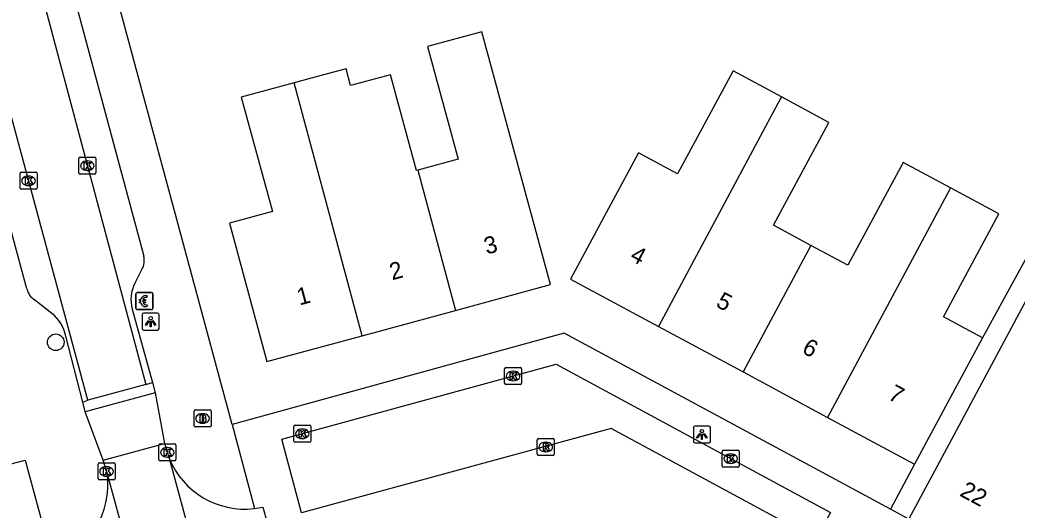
# Model space of a CAD drawing. Extents: x 159265 to 160143, y 383413 to 384319.
# Drawn here: x 159811.3 to 159869.9, y 383863.5 to 383892.3 of the extents above; entities that cross this region are included whole.
import ezdxf

# ---------------------------------------------------------------- set-up
doc = ezdxf.new("R2010")
doc.units = 0
for name, color, linetype in [('IMGEO_Betaalautomaat', 7, 'Continuous'), ('IMGEO_Boom', 7, 'Continuous'), ('IMGEO_Brandkraan', 7, 'Continuous'), ('IMGEO_Kolk', 7, 'Continuous'), ('IMGEO_Lichtpunt', 7, 'Continuous'), ('IMGEO_Pand', 7, 'Continuous'), ('IMGEO_Pand_nummerreeks', 7, 'Continuous'), ('IMGEO_Rijbaan_lokaal_open', 7, 'Continuous'), ('IMGEO_Rioolput', 7, 'Continuous'), ('IMGEO_Voetpad_open', 7, 'Continuous')]:
    doc.layers.add(name, color=color, linetype=linetype)

msp = doc.modelspace()

# ---------------------------------------------------------------- linework, layer by layer
at = {"layer": 'IMGEO_Betaalautomaat'}
for p, q in [((159818.135, 383875.319), (159818.135, 383876.16)), ((159818.135, 383876.16), (159818.135, 383875.319)), ((159818.21, 383876.243), (159819.051, 383876.243)), ((159819.051, 383876.243), (159818.21, 383876.243)), ((159818.418, 383875.707), (159818.418, 383875.775)), ((159818.539, 383875.775), (159818.539, 383875.707)), ((159818.797, 383876.048), (159818.78, 383875.948)), ((159819.134, 383876.169), (159819.134, 383875.328)), ((159819.134, 383875.328), (159819.134, 383876.169)), ((159819.06, 383875.244), (159818.219, 383875.244)), ((159818.219, 383875.244), (159819.06, 383875.244)), ((159818.784, 383875.542), (159818.806, 383875.455))]:
    msp.add_line(p, q, dxfattribs=at)
for points in [[(159818.418, 383875.775), (159818.349, 383875.775), (159818.349, 383875.844), (159818.428, 383875.844)], [(159818.423, 383875.638), (159818.349, 383875.638), (159818.349, 383875.707), (159818.418, 383875.707)], [(159818.55, 383875.844), (159818.697, 383875.844), (159818.697, 383875.775), (159818.539, 383875.775)], [(159818.539, 383875.707), (159818.697, 383875.707), (159818.697, 383875.638), (159818.553, 383875.638)]]:
    msp.add_lwpolyline(points, dxfattribs=at)
for centre, radius, start, end in [((159818.213, 383876.166), 0.0779, 92.4484, 184.28452), ((159818.213, 383876.166), 0.0779, 92.4484, 184.28452), ((159818.711, 383875.768), 0.293, 73.01398, 165.01395), ((159818.717, 383875.781), 0.179, 69.32359, 159.56827), ((159819.057, 383876.166), 0.0779, 2.4484, 94.28452), ((159819.057, 383876.166), 0.0779, 2.4484, 94.28452), ((159818.213, 383875.322), 0.0779, 182.4484, 274.28452), ((159818.213, 383875.322), 0.0779, 182.4484, 274.28452), ((159818.684, 383875.693), 0.267, 191.80956, 297.03891), ((159818.717, 383875.708), 0.179, 202.76249, 291.86925), ((159819.057, 383875.322), 0.0779, 272.4484, 4.28452), ((159819.057, 383875.322), 0.0779, 272.4484, 4.28452)]:
    msp.add_arc(centre, radius, start, end, dxfattribs=at)
at = {"layer": 'IMGEO_Boom'}
msp.add_circle((159813.417, 383873.324), 0.489, dxfattribs=at)
at = {"layer": 'IMGEO_Brandkraan'}
for p, q in [((159821.552, 383868.422), (159821.552, 383869.274)), ((159821.627, 383869.348), (159822.479, 383869.348)), ((159822.553, 383869.274), (159822.553, 383868.422)), ((159822.04, 383869.128), (159822.065, 383869.128)), ((159822.479, 383868.348), (159821.627, 383868.348)), ((159822.063, 383868.568), (159822.038, 383868.568))]:
    msp.add_line(p, q, dxfattribs=at)
for points in [[(159821.552, 383868.422), (159821.552, 383869.274)], [(159821.627, 383869.348), (159822.479, 383869.348)], [(159822.553, 383869.274), (159822.553, 383868.422)], [(159821.9, 383869.048), (159821.9, 383868.648), (159822.113, 383868.648)], [(159822.131, 383869.048), (159821.9, 383869.048)], [(159822.079, 383868.967), (159822.025, 383868.967), (159822.025, 383868.891)], [(159822.025, 383868.891), (159822.078, 383868.891)], [(159822.087, 383868.815), (159822.025, 383868.815), (159822.025, 383868.734)], [(159822.025, 383868.734), (159822.087, 383868.734)], [(159822.479, 383868.348), (159821.627, 383868.348)]]:
    msp.add_lwpolyline(points, dxfattribs=at)
for centre, radius, start, end in [((159821.629, 383869.272), 0.0765, 91.55205, 178.44795), ((159821.629, 383869.272), 0.0765, 91.55205, 178.44795), ((159822.477, 383869.272), 0.0765, 1.55205, 88.44795), ((159822.477, 383869.272), 0.0765, 1.55205, 88.44795), ((159822.08, 383868.929), 0.0379, 267.82845, 90.93552), ((159822.088, 383868.774), 0.0404, 269.87594, 90.50774), ((159822.119, 383868.899), 0.251, 268.66757, 293.53466), ((159822.135, 383868.903), 0.145, 59.4692, 91.53667), ((159822.16, 383868.95), 0.0922, 285.51372, 58.15012), ((159822.165, 383868.758), 0.105, 301.31148, 78.98903), ((159821.629, 383868.424), 0.0765, 181.55205, 268.44795), ((159821.629, 383868.424), 0.0765, 181.55205, 268.44795), ((159822.477, 383868.424), 0.0765, 271.55205, 358.44795), ((159822.477, 383868.424), 0.0765, 271.55205, 358.44795)]:
    msp.add_arc(centre, radius, start, end, dxfattribs=at)
for centre, major_axis, ratio, start_param, end_param in [((159822.039, 383868.848), (-0.387, 0.002), 0.722429, 4.712389, 7.853982), ((159822.064, 383868.848), (-0.39, 0.002), 0.717154, 1.570796, 4.712389)]:
    msp.add_ellipse(centre, major_axis=major_axis, ratio=ratio, start_param=start_param, end_param=end_param, dxfattribs=at)
at = {"layer": 'IMGEO_Kolk'}
for p, q in [((159814.779, 383883.275), (159814.779, 383884.127)), ((159814.854, 383884.201), (159815.706, 383884.201)), ((159815.267, 383883.981), (159815.292, 383883.981)), ((159815.78, 383884.127), (159815.78, 383883.275)), ((159811.395, 383883.316), (159812.247, 383883.316)), ((159815.29, 383883.421), (159815.265, 383883.421)), ((159811.32, 383882.39), (159811.32, 383883.242)), ((159811.808, 383883.096), (159811.833, 383883.096)), ((159812.321, 383883.242), (159812.321, 383882.39)), ((159815.706, 383883.201), (159814.854, 383883.201)), ((159812.247, 383882.316), (159811.395, 383882.316)), ((159811.831, 383882.536), (159811.806, 383882.536)), ((159839.813, 383870.913), (159839.813, 383871.765)), ((159839.888, 383871.839), (159840.74, 383871.839)), ((159840.301, 383871.619), (159840.326, 383871.619)), ((159840.814, 383871.765), (159840.814, 383870.913)), ((159840.324, 383871.059), (159840.299, 383871.059)), ((159840.74, 383870.839), (159839.888, 383870.839)), ((159827.415, 383867.521), (159827.415, 383868.373)), ((159827.49, 383868.447), (159828.342, 383868.447)), ((159827.903, 383868.227), (159827.928, 383868.227)), ((159828.416, 383868.373), (159828.416, 383867.521)), ((159827.926, 383867.667), (159827.901, 383867.667)), ((159819.478, 383866.425), (159819.478, 383867.277)), ((159819.553, 383867.351), (159820.405, 383867.351)), ((159819.966, 383867.131), (159819.991, 383867.131)), ((159820.479, 383867.277), (159820.479, 383866.425)), ((159828.342, 383867.447), (159827.49, 383867.447)), ((159852.604, 383866.06), (159852.604, 383866.912)), ((159852.679, 383866.986), (159853.531, 383866.986)), ((159853.605, 383866.912), (159853.605, 383866.06)), ((159820.405, 383866.351), (159819.553, 383866.351)), ((159819.989, 383866.571), (159819.964, 383866.571)), ((159853.092, 383866.766), (159853.117, 383866.766)), ((159815.908, 383865.306), (159815.908, 383866.158)), ((159815.983, 383866.232), (159816.835, 383866.232)), ((159816.396, 383866.012), (159816.421, 383866.012)), ((159816.909, 383866.158), (159816.909, 383865.306)), ((159853.531, 383865.986), (159852.679, 383865.986)), ((159853.115, 383866.206), (159853.09, 383866.206)), ((159816.835, 383865.232), (159815.983, 383865.232)), ((159816.419, 383865.452), (159816.394, 383865.452))]:
    msp.add_line(p, q, dxfattribs=at)
for points in [[(159814.779, 383883.275), (159814.779, 383884.127)], [(159814.854, 383884.201), (159815.706, 383884.201)], [(159815.1, 383883.901), (159815.223, 383883.901), (159815.223, 383883.75), (159815.353, 383883.901), (159815.517, 383883.901), (159815.371, 383883.75), (159815.524, 383883.501), (159815.372, 383883.501), (159815.287, 383883.665), (159815.223, 383883.598), (159815.223, 383883.501), (159815.1, 383883.501), (159815.1, 383883.901)], [(159815.78, 383884.127), (159815.78, 383883.275)], [(159811.395, 383883.316), (159812.247, 383883.316)], [(159811.32, 383882.39), (159811.32, 383883.242)], [(159811.641, 383883.016), (159811.764, 383883.016), (159811.764, 383882.865), (159811.894, 383883.016), (159812.058, 383883.016), (159811.912, 383882.865), (159812.065, 383882.616), (159811.913, 383882.616), (159811.828, 383882.78), (159811.764, 383882.713), (159811.764, 383882.616), (159811.641, 383882.616), (159811.641, 383883.016)], [(159812.321, 383883.242), (159812.321, 383882.39)], [(159815.706, 383883.201), (159814.854, 383883.201)], [(159812.247, 383882.316), (159811.395, 383882.316)], [(159839.813, 383870.913), (159839.813, 383871.765)], [(159839.888, 383871.839), (159840.74, 383871.839)], [(159840.814, 383871.765), (159840.814, 383870.913)], [(159840.134, 383871.539), (159840.257, 383871.539), (159840.257, 383871.388), (159840.387, 383871.539), (159840.551, 383871.539), (159840.405, 383871.388), (159840.558, 383871.139), (159840.406, 383871.139), (159840.321, 383871.303), (159840.257, 383871.236), (159840.257, 383871.139), (159840.134, 383871.139), (159840.134, 383871.539)], [(159840.74, 383870.839), (159839.888, 383870.839)], [(159827.415, 383867.521), (159827.415, 383868.373)], [(159827.49, 383868.447), (159828.342, 383868.447)], [(159827.736, 383868.147), (159827.859, 383868.147), (159827.859, 383867.996), (159827.989, 383868.147), (159828.153, 383868.147), (159828.007, 383867.996), (159828.16, 383867.747), (159828.008, 383867.747), (159827.923, 383867.911), (159827.859, 383867.844), (159827.859, 383867.747), (159827.736, 383867.747), (159827.736, 383868.147)], [(159828.416, 383868.373), (159828.416, 383867.521)], [(159819.478, 383866.425), (159819.478, 383867.277)], [(159819.553, 383867.351), (159820.405, 383867.351)], [(159819.799, 383867.051), (159819.922, 383867.051), (159819.922, 383866.9), (159820.052, 383867.051), (159820.216, 383867.051), (159820.07, 383866.9), (159820.223, 383866.651), (159820.071, 383866.651), (159819.986, 383866.815), (159819.922, 383866.748), (159819.922, 383866.651), (159819.799, 383866.651), (159819.799, 383867.051)], [(159820.479, 383867.277), (159820.479, 383866.425)], [(159828.342, 383867.447), (159827.49, 383867.447)], [(159852.604, 383866.06), (159852.604, 383866.912)], [(159852.679, 383866.986), (159853.531, 383866.986)], [(159853.605, 383866.912), (159853.605, 383866.06)], [(159820.405, 383866.351), (159819.553, 383866.351)], [(159852.925, 383866.686), (159853.048, 383866.686), (159853.048, 383866.535), (159853.178, 383866.686), (159853.342, 383866.686), (159853.196, 383866.535), (159853.349, 383866.286), (159853.197, 383866.286), (159853.112, 383866.45), (159853.048, 383866.383), (159853.048, 383866.286), (159852.925, 383866.286), (159852.925, 383866.686)], [(159815.908, 383865.306), (159815.908, 383866.158)], [(159815.983, 383866.232), (159816.835, 383866.232)], [(159816.229, 383865.932), (159816.352, 383865.932), (159816.352, 383865.781), (159816.482, 383865.932), (159816.646, 383865.932), (159816.5, 383865.781), (159816.653, 383865.532), (159816.501, 383865.532), (159816.416, 383865.696), (159816.352, 383865.629), (159816.352, 383865.532), (159816.229, 383865.532), (159816.229, 383865.932)], [(159816.909, 383866.158), (159816.909, 383865.306)], [(159853.531, 383865.986), (159852.679, 383865.986)], [(159816.835, 383865.232), (159815.983, 383865.232)]]:
    msp.add_lwpolyline(points, dxfattribs=at)
for centre, start, end in [((159814.856, 383884.125), 91.55205, 178.44795), ((159814.856, 383884.125), 91.55205, 178.44795), ((159815.704, 383884.125), 1.55205, 88.44795), ((159815.704, 383884.125), 1.55205, 88.44795), ((159811.397, 383883.24), 91.55205, 178.44795), ((159811.397, 383883.24), 91.55205, 178.44795), ((159812.245, 383883.24), 1.55205, 88.44795), ((159812.245, 383883.24), 1.55205, 88.44795), ((159814.856, 383883.277), 181.55205, 268.44795), ((159814.856, 383883.277), 181.55205, 268.44795), ((159815.704, 383883.277), 271.55205, 358.44795), ((159815.704, 383883.277), 271.55205, 358.44795), ((159811.397, 383882.392), 181.55205, 268.44795), ((159811.397, 383882.392), 181.55205, 268.44795), ((159812.245, 383882.392), 271.55205, 358.44795), ((159812.245, 383882.392), 271.55205, 358.44795), ((159839.89, 383871.763), 91.55205, 178.44795), ((159839.89, 383871.763), 91.55205, 178.44795), ((159840.738, 383871.763), 1.55205, 88.44795), ((159840.738, 383871.763), 1.55205, 88.44795), ((159839.89, 383870.915), 181.55205, 268.44795), ((159839.89, 383870.915), 181.55205, 268.44795), ((159840.738, 383870.915), 271.55205, 358.44795), ((159840.738, 383870.915), 271.55205, 358.44795), ((159827.492, 383868.371), 91.55205, 178.44795), ((159827.492, 383868.371), 91.55205, 178.44795), ((159828.34, 383868.371), 1.55205, 88.44795), ((159828.34, 383868.371), 1.55205, 88.44795), ((159827.492, 383867.523), 181.55205, 268.44795), ((159827.492, 383867.523), 181.55205, 268.44795), ((159828.34, 383867.523), 271.55205, 358.44795), ((159828.34, 383867.523), 271.55205, 358.44795), ((159819.555, 383867.275), 91.55205, 178.44795), ((159819.555, 383867.275), 91.55205, 178.44795), ((159820.403, 383867.275), 1.55205, 88.44795), ((159820.403, 383867.275), 1.55205, 88.44795), ((159852.681, 383866.91), 91.55205, 178.44795), ((159852.681, 383866.91), 91.55205, 178.44795), ((159853.529, 383866.91), 1.55205, 88.44795), ((159853.529, 383866.91), 1.55205, 88.44795), ((159819.555, 383866.427), 181.55205, 268.44795), ((159819.555, 383866.427), 181.55205, 268.44795), ((159820.403, 383866.427), 271.55205, 358.44795), ((159820.403, 383866.427), 271.55205, 358.44795), ((159815.985, 383866.156), 91.55205, 178.44795), ((159815.985, 383866.156), 91.55205, 178.44795), ((159816.833, 383866.156), 1.55205, 88.44795), ((159816.833, 383866.156), 1.55205, 88.44795), ((159852.681, 383866.062), 181.55205, 268.44795), ((159852.681, 383866.062), 181.55205, 268.44795), ((159853.529, 383866.062), 271.55205, 358.44795), ((159853.529, 383866.062), 271.55205, 358.44795), ((159815.985, 383865.308), 181.55205, 268.44795), ((159815.985, 383865.308), 181.55205, 268.44795), ((159816.833, 383865.308), 271.55205, 358.44795), ((159816.833, 383865.308), 271.55205, 358.44795)]:
    msp.add_arc(centre, 0.0765, start, end, dxfattribs=at)
for centre, major_axis, ratio, start_param, end_param in [((159815.266, 383883.701), (-0.387, 0.002), 0.722429, 4.712389, 7.853982), ((159815.291, 383883.701), (-0.39, 0.002), 0.717154, 1.570796, 4.712389), ((159811.807, 383882.816), (-0.387, 0.002), 0.722429, 4.712389, 7.853982), ((159811.832, 383882.816), (-0.39, 0.002), 0.717154, 1.570796, 4.712389), ((159840.3, 383871.339), (-0.387, 0.002), 0.722429, 4.712389, 7.853982), ((159840.325, 383871.339), (-0.39, 0.002), 0.717154, 1.570796, 4.712389), ((159827.902, 383867.947), (-0.387, 0.002), 0.722429, 4.712389, 7.853982), ((159827.927, 383867.947), (-0.39, 0.002), 0.717154, 1.570796, 4.712389), ((159819.965, 383866.851), (-0.387, 0.002), 0.722429, 4.712389, 7.853982), ((159819.99, 383866.851), (-0.39, 0.002), 0.717154, 1.570796, 4.712389), ((159853.091, 383866.486), (-0.387, 0.002), 0.722429, 4.712389, 7.853982), ((159853.116, 383866.486), (-0.39, 0.002), 0.717154, 1.570796, 4.712389), ((159816.395, 383865.732), (-0.387, 0.002), 0.722429, 4.712389, 7.853982), ((159816.42, 383865.732), (-0.39, 0.002), 0.717154, 1.570796, 4.712389)]:
    msp.add_ellipse(centre, major_axis=major_axis, ratio=ratio, start_param=start_param, end_param=end_param, dxfattribs=at)
at = {"layer": 'IMGEO_Lichtpunt'}
for p, q in [((159818.503, 383874.942), (159818.503, 383874.135)), ((159818.503, 383874.942), (159818.503, 383874.135)), ((159819.405, 383875.037), (159818.597, 383875.037)), ((159819.405, 383875.037), (159818.597, 383875.037)), ((159819.499, 383874.135), (159819.499, 383874.942)), ((159819.499, 383874.135), (159819.499, 383874.942)), ((159818.597, 383874.041), (159819.405, 383874.041)), ((159818.597, 383874.041), (159819.405, 383874.041)), ((159850.914, 383868.308), (159850.914, 383867.501)), ((159850.914, 383868.308), (159850.914, 383867.501)), ((159851.816, 383868.403), (159851.008, 383868.403)), ((159851.816, 383868.403), (159851.008, 383868.403)), ((159851.91, 383867.501), (159851.91, 383868.308)), ((159851.91, 383867.501), (159851.91, 383868.308)), ((159851.008, 383867.407), (159851.816, 383867.407)), ((159851.008, 383867.407), (159851.816, 383867.407))]:
    msp.add_line(p, q, dxfattribs=at)
for points in [[(159818.877, 383874.606), (159818.916, 383874.578), (159818.728, 383874.316), (159818.69, 383874.343), (159818.877, 383874.606)], [(159818.979, 383874.558), (159819.026, 383874.558), (159819.026, 383874.236), (159818.979, 383874.236), (159818.979, 383874.558)], [(159819.089, 383874.578), (159819.127, 383874.605), (159819.314, 383874.343), (159819.275, 383874.315), (159819.089, 383874.578)], [(159851.288, 383867.972), (159851.327, 383867.944), (159851.139, 383867.682), (159851.101, 383867.709), (159851.288, 383867.972)], [(159851.39, 383867.924), (159851.437, 383867.924), (159851.437, 383867.602), (159851.39, 383867.602), (159851.39, 383867.924)], [(159851.5, 383867.944), (159851.538, 383867.971), (159851.725, 383867.709), (159851.686, 383867.681), (159851.5, 383867.944)]]:
    msp.add_lwpolyline(points, dxfattribs=at)
for centre in [(159819.002, 383874.74), (159851.413, 383868.106)]:
    msp.add_circle(centre, 0.0994, dxfattribs=at)
for centre, start, end in [((159818.597, 383874.942), 90, 180), ((159818.597, 383874.942), 90, 180), ((159819.405, 383874.942), 0, 90), ((159819.405, 383874.942), 0, 90), ((159818.597, 383874.135), 180, 270), ((159818.597, 383874.135), 180, 270), ((159819.405, 383874.135), 270, 0), ((159819.405, 383874.135), 270, 360), ((159851.008, 383868.308), 90, 180), ((159851.008, 383868.308), 90, 180), ((159851.816, 383868.308), 0, 90), ((159851.816, 383868.308), 0, 90), ((159851.008, 383867.501), 180, 270), ((159851.008, 383867.501), 180, 270), ((159851.816, 383867.501), 270, 0), ((159851.816, 383867.501), 270, 360)]:
    msp.add_arc(centre, 0.0946, start, end, dxfattribs=at)
at = {"layer": 'IMGEO_Pand'}
for points in [[(159836.926, 383875.2), (159842.516, 383876.72), (159841.205, 383881.546), (159838.479, 383891.572), (159835.284, 383890.704), (159837.082, 383884.095), (159834.703, 383883.448)], [(159834.703, 383883.448), (159834.639, 383883.431), (159833.11, 383889.05), (159830.757, 383888.41), (159830.488, 383889.4), (159829.156, 383889.038), (159827.43, 383888.569)], [(159856.086, 383887.751), (159853.247, 383889.279), (159849.985, 383883.217), (159847.677, 383884.458), (159846.058, 383881.45), (159843.688, 383877.043), (159848.86, 383874.26)], [(159827.43, 383888.569), (159824.33, 383887.726), (159826.156, 383881.009), (159823.628, 383880.322), (159825.839, 383872.186), (159831.437, 383873.708)], [(159831.437, 383873.708), (159827.43, 383888.569)], [(159856.086, 383887.751), (159856.03, 383887.647), (159848.86, 383874.26)], [(159857.814, 383879.021), (159855.619, 383880.202), (159858.874, 383886.251), (159856.086, 383887.751)], [(159866.027, 383882.401), (159863.241, 383883.9), (159859.986, 383877.851), (159857.814, 383879.021)], [(159834.703, 383883.448), (159836.926, 383875.2)], [(159866.027, 383882.401), (159865.965, 383882.285), (159858.802, 383868.911)], [(159867.913, 383873.583), (159865.612, 383874.821), (159868.868, 383880.871), (159866.027, 383882.401)], [(159857.814, 383879.021), (159853.831, 383871.586)], [(159863.575, 383862.933), (159865.944, 383867.338), (159870.821, 383876.41)], [(159831.437, 383873.708), (159836.926, 383875.2)], [(159848.86, 383874.26), (159853.831, 383871.586)], [(159867.913, 383873.583), (159866.288, 383870.562), (159863.919, 383866.158)], [(159853.831, 383871.586), (159858.802, 383868.911)], [(159858.802, 383868.911), (159863.919, 383866.158)]]:
    msp.add_lwpolyline(points, dxfattribs=at)
at = {"layer": 'IMGEO_Rijbaan_lokaal_open'}
for points in [[(159807.004, 383914.628), (159810.359, 383902.14), (159818.708, 383870.849)], [(159815.309, 383869.922), (159806.832, 383901.268), (159803.49, 383913.682)], [(159818.708, 383870.849), (159815.309, 383869.922)], [(159818.708, 383870.849), (159819.103, 383870.957)], [(159819.103, 383870.957), (159819.268, 383870.356)], [(159815.004, 383869.813), (159815.309, 383869.922)], [(159815.151, 383869.24), (159815.004, 383869.813)], [(159819.268, 383870.356), (159815.151, 383869.24)], [(159858.117, 383861.754), (159846.081, 383868.251), (159827.864, 383863.295)], [(159816.206, 383866.393), (159819.812, 383867.366)], [(159819.812, 383867.366), (159820.087, 383866.52)], [(159816.455, 383865.576), (159816.206, 383866.393)], [(159820.087, 383866.52), (159821.446, 383861.508), (159825.844, 383862.726)], [(159813.56, 383859.369), (159817.836, 383860.538), (159816.455, 383865.576)]]:
    msp.add_lwpolyline(points, dxfattribs=at)
at = {"layer": 'IMGEO_Rioolput'}
for p, q in [((159841.734, 383866.741), (159841.734, 383867.593)), ((159841.809, 383867.667), (159842.661, 383867.667)), ((159842.735, 383867.593), (159842.735, 383866.741)), ((159842.245, 383866.887), (159842.22, 383866.887)), ((159842.222, 383867.447), (159842.247, 383867.447)), ((159842.661, 383866.667), (159841.809, 383866.667))]:
    msp.add_line(p, q, dxfattribs=at)
for points in [[(159841.734, 383866.741), (159841.734, 383867.593)], [(159841.809, 383867.667), (159842.661, 383867.667)], [(159842.735, 383867.593), (159842.735, 383866.741)], [(159842.323, 383867.365), (159842.071, 383867.367), (159842.071, 383866.967)], [(159842.071, 383866.967), (159842.195, 383866.967), (159842.195, 383867.129), (159842.206, 383867.129)], [(159842.249, 383867.286), (159842.195, 383867.286), (159842.195, 383867.205)], [(159842.195, 383867.205), (159842.247, 383867.205)], [(159842.253, 383867.1), (159842.324, 383866.967), (159842.464, 383866.967), (159842.399, 383867.093)], [(159842.661, 383866.667), (159841.809, 383866.667)]]:
    msp.add_lwpolyline(points, dxfattribs=at)
for centre, radius, start, end in [((159841.811, 383867.591), 0.0765, 91.55205, 178.44795), ((159841.811, 383867.591), 0.0765, 91.55205, 178.44795), ((159842.659, 383867.591), 0.0765, 1.55205, 88.44795), ((159842.659, 383867.591), 0.0765, 1.55205, 88.44795), ((159842.205, 383867.076), 0.0533, 26.02933, 88.69889), ((159842.231, 383867.394), 0.19, 274.7715, 282.96867), ((159842.255, 383867.19), 0.0964, 77.00612, 93.18647), ((159842.269, 383867.247), 0.0378, 276.66336, 79.67722), ((159842.322, 383867.255), 0.109, 350.36119, 89.41601), ((159842.32, 383867.255), 0.112, 277.58423, 350.98172), ((159842.304, 383867.04), 0.108, 29.51342, 73.79051), ((159841.811, 383866.743), 0.0765, 181.55205, 268.44795), ((159841.811, 383866.743), 0.0765, 181.55205, 268.44795), ((159842.659, 383866.743), 0.0765, 271.55205, 358.44795), ((159842.659, 383866.743), 0.0765, 271.55205, 358.44795)]:
    msp.add_arc(centre, radius, start, end, dxfattribs=at)
for centre, major_axis, ratio, start_param, end_param in [((159842.221, 383867.167), (-0.387, 0.002), 0.722429, 4.712389, 7.853982), ((159842.246, 383867.167), (-0.39, 0.002), 0.717154, 1.570796, 4.712389)]:
    msp.add_ellipse(centre, major_axis=major_axis, ratio=ratio, start_param=start_param, end_param=end_param, dxfattribs=at)
at = {"layer": 'IMGEO_Voetpad_open'}
for points in [[(159812.898, 383899.582), (159818.596, 383878.385)], [(159811.723, 383876.47), (159805.991, 383897.646)], [(159877.476, 383896.498), (159879.774, 383895.188), (159878.358, 383892.676), (159867.913, 383873.583)], [(159823.801, 383868.486), (159817.022, 383893.625)], [(159818.491, 383877.62), (159818.07, 383876.796)], [(159813.19, 383875.025), (159812.168, 383875.816)], [(159817.915, 383875.274), (159819.103, 383870.957)], [(159815.004, 383869.813), (159814.01, 383873.693)], [(159862.494, 383863.516), (159843.313, 383873.858), (159823.801, 383868.486)], [(159827.864, 383863.295), (159826.716, 383867.62), (159842.848, 383872.034), (159858.979, 383863.311), (159858.117, 383861.754)], [(159819.268, 383870.356), (159819.812, 383867.366)], [(159816.206, 383866.393), (159815.151, 383869.24)], [(159823.801, 383868.486), (159825.103, 383863.552)], [(159811.616, 383866.39), (159812.893, 383861.69), (159811.189, 383861.229), (159809.887, 383865.939), (159811.616, 383866.39)], [(159863.919, 383866.158), (159862.494, 383863.516)], [(159825.103, 383863.552), (159825.597, 383863.637), (159825.844, 383862.726)], [(159863.575, 383862.933), (159862.494, 383863.516)]]:
    msp.add_lwpolyline(points, dxfattribs=at)
for centre, radius, start, end in [((159817.57, 383878.136), 1.056, 330.73692, 13.63249), ((159812.8, 383876.725), 1.107, 193.29449, 235.17046), ((159819.924, 383875.838), 2.086, 152.67804, 195.69208), ((159811.775, 383873.235), 2.282, 11.57048, 51.66372), ((159824.533, 383868.311), 4.793, 201.94044, 276.83339), ((159811.403, 383865.012), 5.083, 291.73997, 6.37397)]:
    msp.add_arc(centre, radius, start, end, dxfattribs=at)

# ---------------------------------------------------------------- texts
at = {"layer": 'IMGEO_Pand_nummerreeks'}
for s, rotation, p in [('3', 15.19484, (159838.758, 383878.473)), ('4', 331.70161, (159847.121, 383878.18)), ('2', 15.19484, (159833.197, 383876.963)), ('1', 15.19484, (159827.75, 383875.483)), ('5', 331.70161, (159852.178, 383875.457)), ('6', 331.70161, (159857.235, 383872.734)), ('7', 331.70161, (159862.292, 383870.011)), ('22', 331.71307, (159866.514, 383864.329))]:
    msp.add_text(s, height=1, rotation=rotation, dxfattribs=at).set_placement(p)

doc.saveas('drawing.dxf')
